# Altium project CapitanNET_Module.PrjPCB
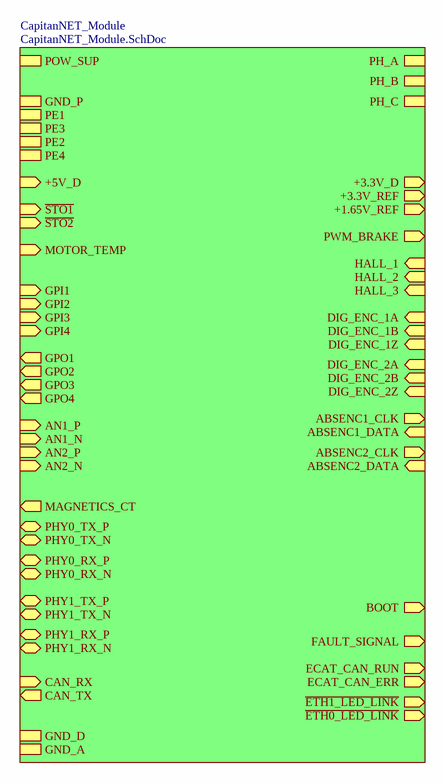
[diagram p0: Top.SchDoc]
2 sheets, 12 parts. Net scope: hierarchical (ports join the sheet entries above them; power ports are global).
Board file: CapitanNET_Module.PcbDoc
Sheets:
  Top.SchDoc
    CapitanNET_Module = CapitanNET_Module.SchDoc

## Sheet Top.SchDoc: CAP-NET
size A3; Organization: Ingenia Motion Control; Address1: Carrer Avila, 124, 2B; Address2: 08018 Barcelona Spain; Address3: www.ingeniamc.com; Address4: www.ingeniamc.com; Revision: 1.0.0; Documentation: https://doc.ingeniamc.com/x/dQH_Bg

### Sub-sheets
CapitanNET_Module = CapitanNET_Module.SchDoc: MOTOR_TEMP (in), ECAT_CAN_RUN (out), DIG_ENC_2A (in), CAN_RX (in), DIG_ENC_1Z (in), AN1_N (in), DIG_ENC_2Z (in), HALL_1 (in), ~{STO1} (in), ~{ETH0_LED_LINK} (out), +5V_D (in), DIG_ENC_1A (in), PWM_BRAKE (out), PHY0_TX_N (bidir), CAN_TX (out), GPO3 (out), ABSENC1_DATA (in), GPO1 (out), +3.3V_D (out), GPI2 (in), HALL_3 (in), HALL_2 (in), AN1_P (in), +3.3V_REF (out), ABSENC2_DATA (in), PHY0_TX_P (bidir), GPO4 (out), DIG_ENC_1B (in), DIG_ENC_2B (in), ABSENC1_CLK (out), PE1, ECAT_CAN_ERR (out), GND_A, GPO2 (out), PH_A, PH_B, PH_C, ABSENC2_CLK (out), GPI3 (in), +1.65V_REF (out), PHY0_RX_P (bidir), GPI1 (in), PHY1_RX_P (bidir), PE2, PHY1_TX_N (bidir), FAULT_SIGNAL (out), POW_SUP, GND_P, ~{STO2} (in), PHY1_TX_P (bidir), PHY1_RX_N (bidir), ~{ETH1_LED_LINK} (out), GND_D, PE3, GPI4 (in), PE4, PHY0_RX_N (bidir), MAGNETICS_CT (out), AN2_P (in), AN2_N (in), BOOT (out)

## Sheet CapitanNET_Module.SchDoc: CAP-NET
size A3; Organization: Ingenia Motion Control; Address1: Carrer Avila, 124, 2B; Address2: 08018 Barcelona Spain; Address3: www.ingeniamc.com; Address4: www.ingeniamc.com; Revision: 1.0.0; Documentation: https://doc.ingeniamc.com/x/dQH_Bg
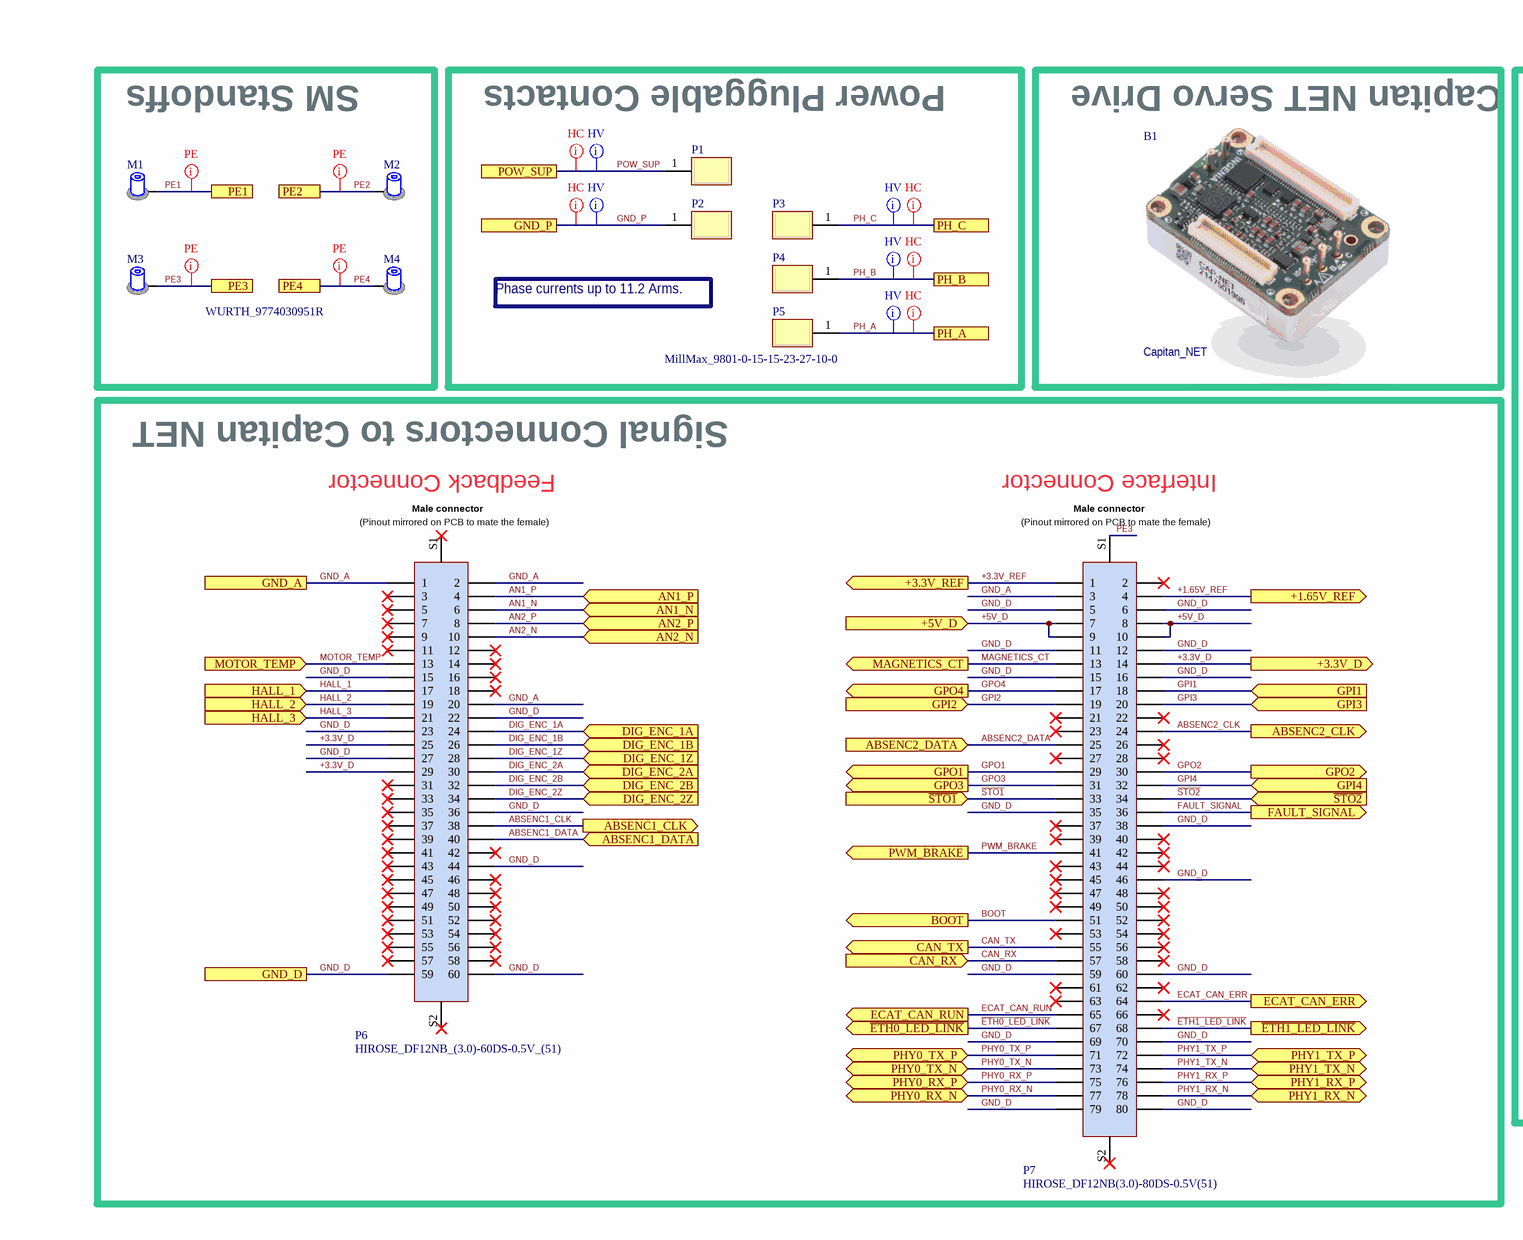
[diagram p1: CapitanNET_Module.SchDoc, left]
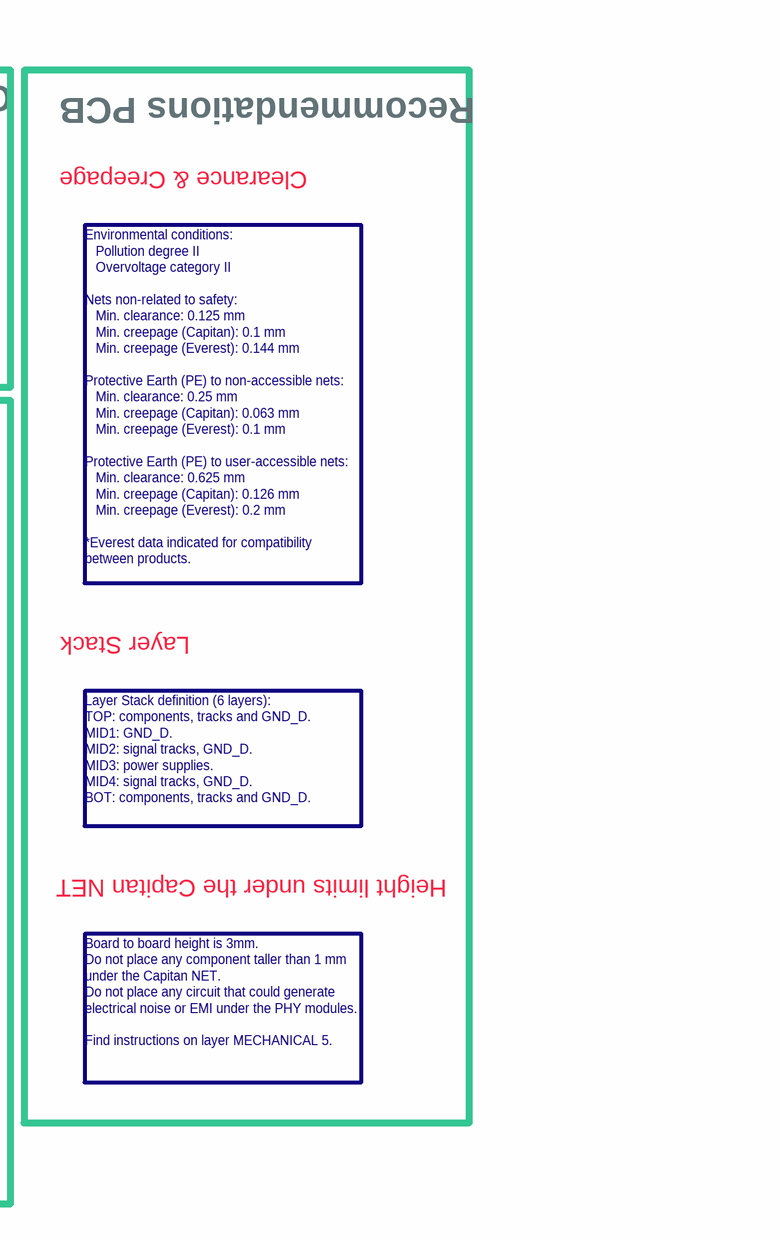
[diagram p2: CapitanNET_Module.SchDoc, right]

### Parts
B1  Capitan_NET  [CAPITAN_NET]
M1  (no value)  [WURTH_9774030951R]
M2  (no value)  [WURTH_9774030951R]
M3  (no value)  [WURTH_9774030951R]
M4  WURTH_9774030951R  [WURTH_9774030951R]
P1  (no value)  [MillMax_9801-0-15-15-23-27-10-0]
P2  (no value)  [MillMax_9801-0-15-15-23-27-10-0]
P3  (no value)  [MillMax_9801-0-15-15-23-27-10-0]
P4  (no value)  [MillMax_9801-0-15-15-23-27-10-0]
P5  (no value)  [MillMax_9801-0-15-15-23-27-10-0]
P6  HIROSE_DF12NB_(3.0)-60DS-0.5V_(51)  [HIROSE_DF12NB(3.0)-60DS-0.5V(51)]
P7  HIROSE_DF12NB(3.0)-80DS-0.5V(51)  [HIROSE_DF12NB(3.0)-80DS-0.5V(51)]

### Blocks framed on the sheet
SM Standoffs: M1-M4
Power Pluggable Contacts: P1-P5
Capitan NET Servo Drive: B1
Signal Connectors to Capitan NET: P6 P7

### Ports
+1.65V_REF (out), +3.3V_D (out), +3.3V_REF (out), +5V_D (in), ABSENC1_CLK (out), ABSENC1_DATA (in), ABSENC2_CLK (out), ABSENC2_DATA (in), AN1_N (in), AN1_P (in), AN2_N (in), AN2_P (in), BOOT (out), CAN_RX (in), CAN_TX (out), DIG_ENC_1A (in), DIG_ENC_1B (in), DIG_ENC_1Z (in), DIG_ENC_2A (in), DIG_ENC_2B (in), DIG_ENC_2Z (in), ECAT_CAN_ERR (out), ECAT_CAN_RUN (out), FAULT_SIGNAL (out), GND_A, GND_D, GND_P, GPI1 (in), GPI2 (in), GPI3 (in), GPI4 (in), GPO1 (out), GPO2 (out), GPO3 (out), GPO4 (out), HALL_1 (in), HALL_2 (in), HALL_3 (in), MAGNETICS_CT (out), MOTOR_TEMP (in), PE1, PE2, PE3, PE4, PH_A, PH_B, PH_C, PHY0_RX_N (bidir), PHY0_RX_P (bidir), PHY0_TX_N (bidir), PHY0_TX_P (bidir), PHY1_RX_N (bidir), PHY1_RX_P (bidir), PHY1_TX_N (bidir), PHY1_TX_P (bidir), POW_SUP, PWM_BRAKE (out), ~{ETH0_LED_LINK} (out), ~{ETH1_LED_LINK} (out), ~{STO1} (in), ~{STO2} (in)

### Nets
+1.65V_REF: P7.4 ; port +1.65V_REF
+3.3V_D: P6.25 P6.29 P7.14 ; port +3.3V_D
+3.3V_REF: P7.1 ; port +3.3V_REF
+5V_D: P7.7 P7.8 P7.9 P7.10 ; port +5V_D
~{ETH0_LED_LINK}: P7.67 ; port ~{ETH0_LED_LINK}
~{ETH1_LED_LINK}: P7.68 ; port ~{ETH1_LED_LINK}
~{STO1}: P7.33 ; port ~{STO1}
~{STO2}: P7.34 ; port ~{STO2}
ABSENC1_CLK: P6.38 ; port ABSENC1_CLK
ABSENC1_DATA: P6.40 ; port ABSENC1_DATA
ABSENC2_CLK: P7.24 ; port ABSENC2_CLK
ABSENC2_DATA: P7.25 ; port ABSENC2_DATA
AN1_N: P6.6 ; port AN1_N
AN1_P: P6.4 ; port AN1_P
AN2_N: P6.10 ; port AN2_N
AN2_P: P6.8 ; port AN2_P
BOOT: P7.51 ; port BOOT
CAN_RX: P7.57 ; port CAN_RX
CAN_TX: P7.55 ; port CAN_TX
DIG_ENC_1A: P6.24 ; port DIG_ENC_1A
DIG_ENC_1B: P6.26 ; port DIG_ENC_1B
DIG_ENC_1Z: P6.28 ; port DIG_ENC_1Z
DIG_ENC_2A: P6.30 ; port DIG_ENC_2A
DIG_ENC_2B: P6.32 ; port DIG_ENC_2B
DIG_ENC_2Z: P6.34 ; port DIG_ENC_2Z
ECAT_CAN_ERR: P7.64 ; port ECAT_CAN_ERR
ECAT_CAN_RUN: P7.65 ; port ECAT_CAN_RUN
FAULT_SIGNAL: P7.36 ; port FAULT_SIGNAL
GND_A: P6.1 P6.2 P6.20 P7.3 ; port GND_A
GND_D: P6.15 P6.22 P6.23 P6.27 P6.36 P6.44 P6.59 P6.60 P7.5 P7.6 P7.11 P7.12 P7.15 P7.16 P7.35 P7.38 P7.46 P7.59 P7.60 P7.69 P7.70 P7.79 P7.80 ; port GND_D
GND_P: P2.1 ; port GND_P
GPI1: P7.18 ; port GPI1
GPI2: P7.19 ; port GPI2
GPI3: P7.20 ; port GPI3
GPI4: P7.32 ; port GPI4
GPO1: P7.29 ; port GPO1
GPO2: P7.30 ; port GPO2
GPO3: P7.31 ; port GPO3
GPO4: P7.17 ; port GPO4
HALL_1: P6.17 ; port HALL_1
HALL_2: P6.19 ; port HALL_2
HALL_3: P6.21 ; port HALL_3
MAGNETICS_CT: P7.13 ; port MAGNETICS_CT
MOTOR_TEMP: P6.13 ; port MOTOR_TEMP
PE1: M1.1 ; port PE1
PE2: M2.1 ; port PE2
PE3: M3.1 P7.S1(Shield2) ; port PE3
PE4: M4.1 ; port PE4
PH_A: P5.1 ; port PH_A
PH_B: P4.1 ; port PH_B
PH_C: P3.1 ; port PH_C
PHY0_RX_N: P7.77 ; port PHY0_RX_N
PHY0_RX_P: P7.75 ; port PHY0_RX_P
PHY0_TX_N: P7.73 ; port PHY0_TX_N
PHY0_TX_P: P7.71 ; port PHY0_TX_P
PHY1_RX_N: P7.78 ; port PHY1_RX_N
PHY1_RX_P: P7.76 ; port PHY1_RX_P
PHY1_TX_N: P7.74 ; port PHY1_TX_N
PHY1_TX_P: P7.72 ; port PHY1_TX_P
POW_SUP: P1.1 ; port POW_SUP
PWM_BRAKE: P7.41 ; port PWM_BRAKE

Not connected (* = marked no-connect by the designer): P6 3* 5* 7* 9* 11* 12* 14* 16* 18* 31* 33* 35* 37* 39* 41* 42* 43* 45* 46* 47* 48* 49* 50* 51* 52* 53* 54* 55* 56* 57* 58* S1(shield1)* S2(Shield2)*; P7 2* 21* 22* 23* 26* 27* 28* 37* 39* 40* 42* 43* 44* 45* 47* 48* 49* 50* 52* 53* 54* 56* 58* 61* 62* 63* 66* S2(Shield2)*

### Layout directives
net class ProtectiveEarth: PE1, PE2, PE3, PE4
net class HighCurrent: GND_P, PH_A, PH_B, PH_C, POW_SUP
net class HighVoltage: GND_P, PH_A, PH_B, PH_C, POW_SUP

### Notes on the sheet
- Recommendations PCB
- Clearance & Creepage
- Phase currents up to 11.2 Arms.
- Feedback Connector
- Interface Connector
- Environmental conditions:
  Pollution degree II
  Overvoltage category II
  Nets non-related to safety:
  Min. clearance: 0.125 mm
  Min. creepage (Capitan): 0.1 mm
  Min. creepage (Everest): 0.144 mm
  Protective Earth (PE) to non-accessible nets:
  Min. clearance: 0.25 mm
  Min. creepage (Capitan): 0.063 mm
  Min. creepage (Everest): 0.1 mm
  Protective Earth (PE) to user-accessible nets:
  Min. clearance: 0.625 mm
  Min. creepage (Capitan): 0.126 mm
  Min. creepage (Everest): 0.2 mm
  *Everest data indicated for compatibility between products.
- Layer Stack
- Layer Stack definition (6 layers):
  TOP: components, tracks and GND_D.
  MID1: GND_D.
  MID2: signal tracks, GND_D.
  MID3: power supplies.
  MID4: signal tracks, GND_D.
  BOT: components, tracks and GND_D.
- Height limits under the Capitan NET
- Board to board height is 3mm.
  Do not place any component taller than 1 mm under the Capitan NET.
  Do not place any circuit that could generate electrical noise or EMI under the PHY modules.
  Find instructions on layer MECHANICAL 5.

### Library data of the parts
B1 = Capitan_NET: Capitan NET high-performance Servo Drive from Ingenia Motion Control.; ManufacturerPN: CAP-NET-E; IsPreferred: 0; IngeniaID: 5083; TemperatureMaxC: 85; TemperatureMinC: -40; MTBF55h: 600000; AlternativePN: CAP-NET-C
M1-M3 = SPACER_SMD_ROUND_M2.5x3mm_NO_THREAD: Round SMD standoff M2.5 3mm height No Threaded Steel; ManufacturerName: Wurth Electronics Inc; ManufacturerPN: 9774030951R; IsPreferred: 0; IngeniaID: 4248; TemperatureMaxC: 200; TemperatureMinC: -40
M4 = SPACER_SMD_ROUND_M2.5x3mm_NO_THREAD: Round SMD standoff M2.5 3mm height No Threaded Steel; ManufacturerName: Wurth Electronics Inc; IsPreferred: 0; IngeniaID: 4248; TemperatureMaxC: 200; TemperatureMinC: -40
P1-P5 = MillMax_9801-0-15-15-23-27-10-0: 1pin, receptacle for MillMax 6142, blind end; IsPreferred: 0; IngeniaID: 4685; TemperatureMaxC: 125; TemperatureMinC: -55
P6 = HIROSE_DF12NB_(3.0)-60DS-0.5V_(51): Connector SMD Mezzanine, Black 60 ways, 0.5mm pitch, 3mm stack height. Male; ManufacturerName: Hirose; ManufacturerPN: DF12NB(3.0)-60DS-0.5V(51); IsPreferred: 0; IngeniaID: 5203; TemperatureMaxC: 125; TemperatureMinC: -55
P7 = HIROSE_DF12NB(3.0)-80DS-0.5V(51): Connector SMD Mezzanine, 80 ways, 0.5mm pitch, 3mm stack height. Male with metal fitting; ManufacturerName: Hirose; IsPreferred: 0; IngeniaID: 5173; TemperatureMaxC: 125; TemperatureMinC: -45; MTBF55h: 176336644; AlternativePN: DF12(3.0)-80DS-0.5V(86)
